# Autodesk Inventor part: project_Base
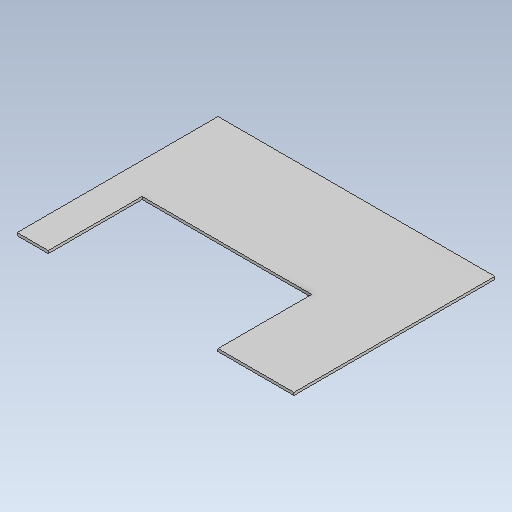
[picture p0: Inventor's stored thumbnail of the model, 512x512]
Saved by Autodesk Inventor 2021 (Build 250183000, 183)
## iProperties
Created: 2026-10
Part Number: project_Base
Material: Steel
Document SubType Name: Modeling
Designer: hp
Density: 7.85 g/cm^3
Appearance: Default
Author: hp
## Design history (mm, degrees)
feature "Body1"
body "Solid1"
